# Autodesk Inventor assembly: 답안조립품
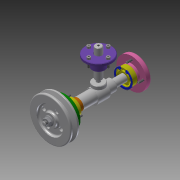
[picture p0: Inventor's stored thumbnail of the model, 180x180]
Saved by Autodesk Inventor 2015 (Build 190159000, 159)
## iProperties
Created: 2020-08
Part Number: 답안조립품
Document SubType Name: Assembly
Designer: 101548
Author: 101548
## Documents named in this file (18)
- C:\Users\101548\Desktop\700806V1037\답안조립품.iam
- C:\Users\101548\Desktop\700806V1037\V-벨트풀리.ipt
- C:\Users\101548\Desktop\700806V1037\너트 M8.ipt
- C:\Users\101548\Desktop\700806V1037\뒤커버.ipt
- C:\Users\101548\Desktop\700806V1037\멈춤링 15x1.ipt
- C:\Users\101548\Desktop\700806V1037\멈춤링 35x1.6.ipt
- 멈춤링 35x1.6.ipt
- C:\Users\101548\Desktop\700806V1037\베어링 6202.ipt
- 베어링 6202.ipt
- C:\Users\101548\Desktop\700806V1037\본체.ipt
- C:\Users\101548\Desktop\700806V1037\볼트 M4.ipt
- C:\Users\101548\Desktop\700806V1037\상부커버.ipt
- C:\Users\101548\Desktop\700806V1037\슬라이드.ipt
- C:\Users\101548\Desktop\700806V1037\앞커버.ipt
- C:\Users\101548\Desktop\700806V1037\오일 실 15 30 7.ipt
- C:\Users\101548\Desktop\700806V1037\칼라.ipt
- C:\Users\101548\Desktop\700806V1037\키 3x3x12.ipt
- C:\Users\101548\Desktop\700806V1037\편심축.ipt
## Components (1 placed, 1 different names)
1. V-벨트풀리:1 — 각도:2
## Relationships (1: Angle 1)
- 각도:2 [Angle]: V-벨트풀리:1
